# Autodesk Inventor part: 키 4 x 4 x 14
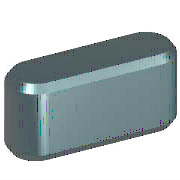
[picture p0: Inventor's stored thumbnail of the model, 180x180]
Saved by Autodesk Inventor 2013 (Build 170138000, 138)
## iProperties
Created: 2012-02
Part Number: 키 4 x 4 x 14
Material: 강철, 연강
Description: 키 및 해당 키홈
Document SubType Name: Modeling
Standard: KS B 1311
Designer: test
Standards Organization: KS
Language: ko-KR
Size Designation: 4 x 4 x 14
Categories: <MemberInstance><Categories><Category DisplayName="샤프트 부품" InternalName="7f7aeb1f-a693-4053-b835-cee3144e0d98" Mnemonic="SHFT"><Category DisplayName="키" Interna
Density: 1 g/cm^3
IsCustomPart: 1
Author: test
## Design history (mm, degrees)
workplane "Work Plane1"
workplane "Work Plane2"
sketch "스케치1"
  geometry: L1 (2, 2)-(12, 2); L2 (12, -2)-(2, -2); L3 (0, 9.4)-(0, -7.4) reference; L4 (-5, 0)-(30, 0) reference; L5 (14, 0)-(14, 7); A1 r 2 centre (2, 0) between (2, 2) and (2, -2); A2 r 2 centre (12, 0) between (12, -2) and (12, 2)
  constraints: 6 end point, 5 point on circle, 4 tangent, 3 point on line, 2 centre point, 1 horizontal, 1 parallel, 1 perpendicular
  dimensions: "d0" = 2 radius of A1 (= 0.5 x PB); "d13" = 2 radius of A2 (= 0.5 x PB); "d14" = 14 distance between parallel lines of L5 L3 (= NLG)
extrude "본체1" new body sketch "스케치1" taper "d3" = 0 deg; stored distance "d4" = 10
workplane "Work Plane3"
body "Solid1"
chamfer "모따기1" distance "d8" = 0.25 (= PHH); stored, may be unused: second distance "d9" = 0.25 (= PHH), angle "d15" = 45 deg
other parameters: "d1" = -2.5 (= -PNT), "d2" = 1.5 (= PH - PNT), "NLG" = 14 [user parameter; used in 3 equation terms], "PB" = 4 [user parameter; used in 2 equation terms], "PNT" = 2.5 [user parameter; used in 2 equation terms], "PH" = 4 [user parameter; used in 1 equation term], "PHH" = 0.25 [user parameter; used in 2 equation terms], "d10" = 0, "d16" = 0, "d17" = 0, "d18" = 0, "PLB2" = 14 (= NLG) [user parameter], "WDMAX" = 12 [user parameter], "PLB1" = 14 (= NLG) [user parameter], "RR" = 0.08 [user parameter], "PUEB" = 1.8 [user parameter]
